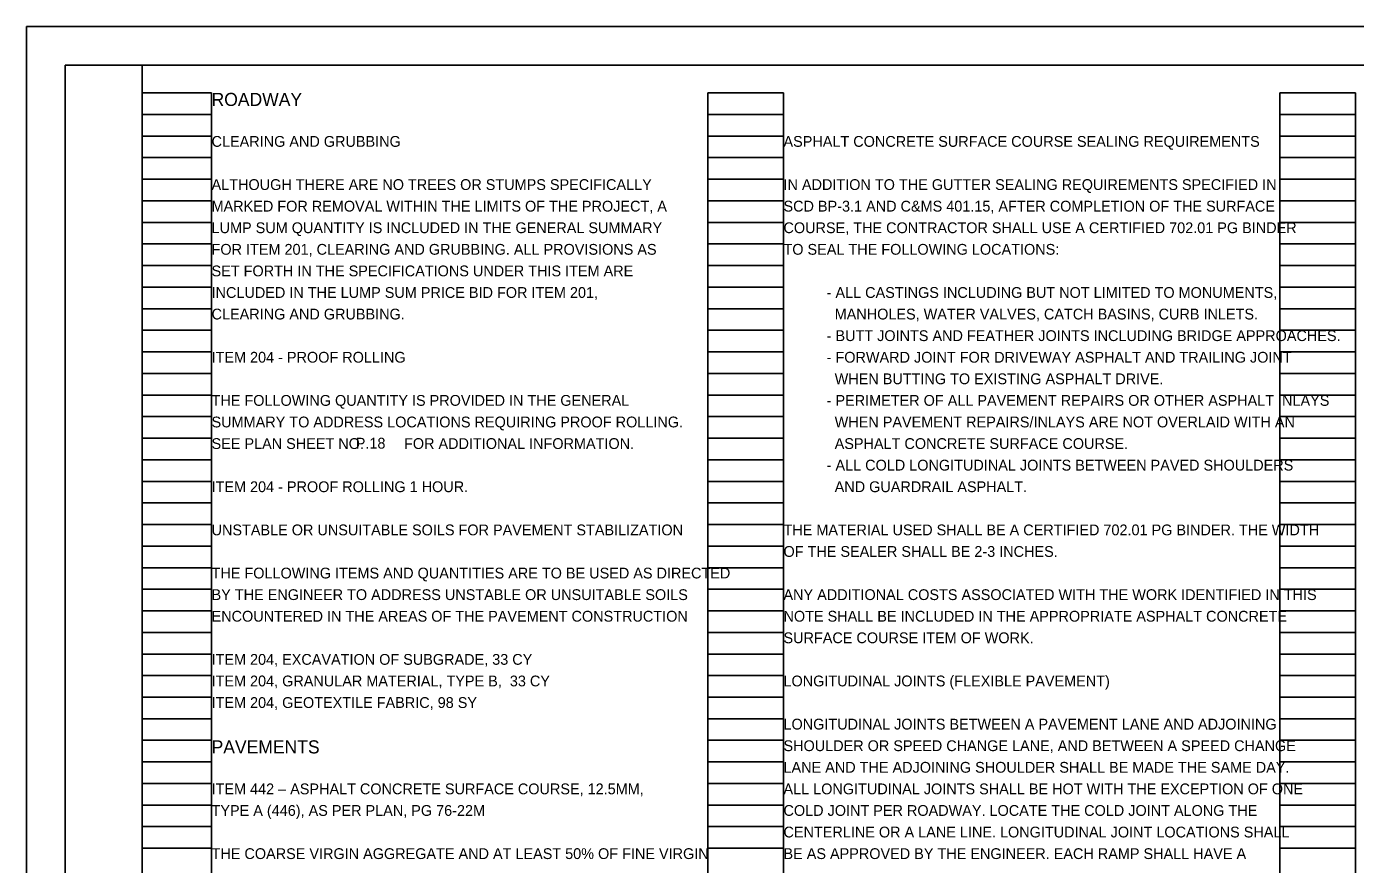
# Model space of a CAD drawing. Extents: x 0 to 34, y -49.5 to 22.
# Drawn here: x 0 to 17.24, y 11.13 to 22 of the extents above; entities that cross this region are included whole.
import ezdxf

# ---------------------------------------------------------------- set-up
doc = ezdxf.new("R2010")
doc.units = 0
for name, color, linetype in [('SH_Border', 7, 'Continuous'), ('SH_Cut_Line', 7, 'Continuous'), ('SH_Data', 7, 'Continuous'), ('SH_Text', 7, 'Continuous')]:
    doc.layers.add(name, color=color, linetype=linetype)

msp = doc.modelspace()

# ---------------------------------------------------------------- linework, layer by layer
at = {"layer": 'SH_Border'}
for points in [[(0.5, 21.5), (1.5, 21.5), (1.5, 0.5), (0.5, 0.5)], [(1.5, 21.5), (33.5, 21.5), (33.5, 0.5), (1.5, 0.5)]]:
    msp.add_lwpolyline(points, close=True, dxfattribs=at)
at = {"layer": 'SH_Cut_Line'}
msp.add_lwpolyline([(0, 0), (34, 0), (34, 22), (0, 22)], close=True, dxfattribs=at)
at = {"layer": 'SH_Data'}
for p, q in [((1.5, 0.98), (1.5, 21.14)), ((1.5, 21.14), (2.4, 21.14)), ((2.4, 0.98), (2.4, 21.14)), ((8.84, 0.98), (8.84, 21.14)), ((8.84, 21.14), (9.82, 21.14)), ((9.82, 0.98), (9.82, 21.14)), ((16.26, 0.98), (16.26, 21.14)), ((16.26, 21.14), (17.24, 21.14)), ((17.24, 0.98), (17.24, 21.14)), ((1.5, 20.86), (2.4, 20.86)), ((8.84, 20.86), (9.82, 20.86)), ((16.26, 20.86), (17.24, 20.86)), ((1.5, 20.58), (2.4, 20.58)), ((8.84, 20.58), (9.82, 20.58)), ((16.26, 20.58), (17.24, 20.58)), ((1.5, 20.3), (2.4, 20.3)), ((8.84, 20.3), (9.82, 20.3)), ((16.26, 20.3), (17.24, 20.3)), ((1.5, 20.02), (2.4, 20.02)), ((8.84, 20.02), (9.82, 20.02)), ((16.26, 20.02), (17.24, 20.02)), ((1.5, 19.74), (2.4, 19.74)), ((8.84, 19.74), (9.82, 19.74)), ((16.26, 19.74), (17.24, 19.74)), ((1.5, 19.46), (2.4, 19.46)), ((8.84, 19.46), (9.82, 19.46)), ((16.26, 19.46), (17.24, 19.46)), ((1.5, 19.18), (2.4, 19.18)), ((8.84, 19.18), (9.82, 19.18)), ((16.26, 19.18), (17.24, 19.18)), ((1.5, 18.9), (2.4, 18.9)), ((8.84, 18.9), (9.82, 18.9)), ((16.26, 18.9), (17.24, 18.9)), ((1.5, 18.62), (2.4, 18.62)), ((8.84, 18.62), (9.82, 18.62)), ((16.26, 18.62), (17.24, 18.62)), ((1.5, 18.34), (2.4, 18.34)), ((8.84, 18.34), (9.82, 18.34)), ((16.26, 18.34), (17.24, 18.34)), ((1.5, 18.06), (2.4, 18.06)), ((8.84, 18.06), (9.82, 18.06)), ((16.26, 18.06), (17.24, 18.06)), ((1.5, 17.78), (2.4, 17.78)), ((8.84, 17.78), (9.82, 17.78)), ((16.26, 17.78), (17.24, 17.78)), ((1.5, 17.5), (2.4, 17.5)), ((8.84, 17.5), (9.82, 17.5)), ((16.26, 17.5), (17.24, 17.5)), ((1.5, 17.22), (2.4, 17.22)), ((8.84, 17.22), (9.82, 17.22)), ((16.26, 17.22), (17.24, 17.22)), ((1.5, 16.94), (2.4, 16.94)), ((8.84, 16.94), (9.82, 16.94)), ((16.26, 16.94), (17.24, 16.94)), ((1.5, 16.66), (2.4, 16.66)), ((8.84, 16.66), (9.82, 16.66)), ((16.26, 16.66), (17.24, 16.66)), ((1.5, 16.38), (2.4, 16.38)), ((8.84, 16.38), (9.82, 16.38)), ((16.26, 16.38), (17.24, 16.38)), ((1.5, 16.1), (2.4, 16.1)), ((8.84, 16.1), (9.82, 16.1)), ((16.26, 16.1), (17.24, 16.1)), ((1.5, 15.82), (2.4, 15.82)), ((8.84, 15.82), (9.82, 15.82)), ((16.26, 15.82), (17.24, 15.82)), ((1.5, 15.54), (2.4, 15.54)), ((8.84, 15.54), (9.82, 15.54)), ((16.26, 15.54), (17.24, 15.54)), ((1.5, 15.26), (2.4, 15.26)), ((8.84, 15.26), (9.82, 15.26)), ((16.26, 15.26), (17.24, 15.26)), ((1.5, 14.98), (2.4, 14.98)), ((8.84, 14.98), (9.82, 14.98)), ((16.26, 14.98), (17.24, 14.98)), ((1.5, 14.7), (2.4, 14.7)), ((8.84, 14.7), (9.82, 14.7)), ((16.26, 14.7), (17.24, 14.7)), ((1.5, 14.42), (2.4, 14.42)), ((8.84, 14.42), (9.82, 14.42)), ((16.26, 14.42), (17.24, 14.42)), ((1.5, 14.14), (2.4, 14.14)), ((8.84, 14.14), (9.82, 14.14)), ((16.26, 14.14), (17.24, 14.14)), ((1.5, 13.86), (2.4, 13.86)), ((8.84, 13.86), (9.82, 13.86)), ((16.26, 13.86), (17.24, 13.86)), ((1.5, 13.58), (2.4, 13.58)), ((8.84, 13.58), (9.82, 13.58)), ((16.26, 13.58), (17.24, 13.58)), ((1.5, 13.3), (2.4, 13.3)), ((8.84, 13.3), (9.82, 13.3)), ((16.26, 13.3), (17.24, 13.3)), ((1.5, 13.02), (2.4, 13.02)), ((8.84, 13.02), (9.82, 13.02)), ((16.26, 13.02), (17.24, 13.02)), ((1.5, 12.74), (2.4, 12.74)), ((8.84, 12.74), (9.82, 12.74)), ((16.26, 12.74), (17.24, 12.74)), ((1.5, 12.46), (2.4, 12.46)), ((8.84, 12.46), (9.82, 12.46)), ((16.26, 12.46), (17.24, 12.46)), ((1.5, 12.18), (2.4, 12.18)), ((8.84, 12.18), (9.82, 12.18)), ((16.26, 12.18), (17.24, 12.18)), ((1.5, 11.9), (2.4, 11.9)), ((8.84, 11.9), (9.82, 11.9)), ((16.26, 11.9), (17.24, 11.9)), ((1.5, 11.62), (2.4, 11.62)), ((8.84, 11.62), (9.82, 11.62)), ((16.26, 11.62), (17.24, 11.62)), ((1.5, 11.34), (2.4, 11.34)), ((8.84, 11.34), (9.82, 11.34)), ((16.26, 11.34), (17.24, 11.34))]:
    msp.add_line(p, q, dxfattribs=at)

# ---------------------------------------------------------------- texts
at = {"layer": 'SH_Text'}
for s, height, p in [('ROADWAY', 0.17, (2.4, 20.97)), ('CLEARING AND GRUBBING', 0.14, (2.4, 20.44)), ('ASPHALT CONCRETE SURFACE COURSE SEALING REQUIREMENTS', 0.14, (9.82, 20.44)), ('ALTHOUGH THERE ARE NO TREES OR STUMPS SPECIFICALLY', 0.14, (2.4, 19.88)), ('IN ADDITION TO THE GUTTER SEALING REQUIREMENTS SPECIFIED IN', 0.14, (9.82, 19.88)), ('MARKED FOR REMOVAL WITHIN THE LIMITS OF THE PROJECT, A', 0.14, (2.4, 19.6)), ('SCD BP-3.1 AND C&MS 401.15, AFTER COMPLETION OF THE SURFACE', 0.14, (9.82, 19.6)), ('LUMP SUM QUANTITY IS INCLUDED IN THE GENERAL SUMMARY', 0.14, (2.4, 19.32)), ('COURSE, THE CONTRACTOR SHALL USE A CERTIFIED 702.01 PG BINDER', 0.14, (9.82, 19.32)), ('FOR ITEM 201, CLEARING AND GRUBBING. ALL PROVISIONS AS', 0.14, (2.4, 19.04)), ('TO SEAL THE FOLLOWING LOCATIONS:', 0.14, (9.82, 19.04)), ('SET FORTH IN THE SPECIFICATIONS UNDER THIS ITEM ARE', 0.14, (2.4, 18.76)), ('INCLUDED IN THE LUMP SUM PRICE BID FOR ITEM 201,', 0.14, (2.4, 18.48)), ('- ALL CASTINGS INCLUDING BUT NOT LIMITED TO MONUMENTS,', 0.14, (10.38, 18.48)), ('CLEARING AND GRUBBING.', 0.14, (2.4, 18.2)), ('  MANHOLES, WATER VALVES, CATCH BASINS, CURB INLETS.', 0.14, (10.38, 18.2)), ('- BUTT JOINTS AND FEATHER JOINTS INCLUDING BRIDGE APPROACHES.', 0.14, (10.38, 17.92)), ('ITEM 204 - PROOF ROLLING', 0.14, (2.4, 17.64)), ('- FORWARD JOINT FOR DRIVEWAY ASPHALT AND TRAILING JOINT', 0.14, (10.38, 17.64)), ('  WHEN BUTTING TO EXISTING ASPHALT DRIVE.', 0.14, (10.38, 17.36)), ('THE FOLLOWING QUANTITY IS PROVIDED IN THE GENERAL', 0.14, (2.4, 17.08)), ('- PERIMETER OF ALL PAVEMENT REPAIRS OR OTHER ASPHALT INLAYS', 0.14, (10.38, 17.08)), ('SUMMARY TO ADDRESS LOCATIONS REQUIRING PROOF ROLLING.', 0.14, (2.4, 16.8)), ('  WHEN PAVEMENT REPAIRS/INLAYS ARE NOT OVERLAID WITH AN', 0.14, (10.38, 16.8)), ('SEE PLAN SHEET NO.          FOR ADDITIONAL INFORMATION.', 0.14, (2.4, 16.52)), ('P.18', 0.14, (4.271, 16.525)), ('  ASPHALT CONCRETE SURFACE COURSE.', 0.14, (10.38, 16.52)), ('- ALL COLD LONGITUDINAL JOINTS BETWEEN PAVED SHOULDERS', 0.14, (10.38, 16.24)), ('ITEM 204 - PROOF ROLLING 1 HOUR.', 0.14, (2.4, 15.96)), ('  AND GUARDRAIL ASPHALT.', 0.14, (10.38, 15.96)), ('UNSTABLE OR UNSUITABLE SOILS FOR PAVEMENT STABILIZATION', 0.14, (2.4, 15.4)), ('THE MATERIAL USED SHALL BE A CERTIFIED 702.01 PG BINDER. THE WIDTH', 0.14, (9.82, 15.4)), ('OF THE SEALER SHALL BE 2-3 INCHES.', 0.14, (9.82, 15.12)), ('THE FOLLOWING ITEMS AND QUANTITIES ARE TO BE USED AS DIRECTED', 0.14, (2.4, 14.84)), ('BY THE ENGINEER TO ADDRESS UNSTABLE OR UNSUITABLE SOILS', 0.14, (2.4, 14.56)), ('ANY ADDITIONAL COSTS ASSOCIATED WITH THE WORK IDENTIFIED IN THIS', 0.14, (9.82, 14.56)), ('ENCOUNTERED IN THE AREAS OF THE PAVEMENT CONSTRUCTION', 0.14, (2.4, 14.28)), ('NOTE SHALL BE INCLUDED IN THE APPROPRIATE ASPHALT CONCRETE', 0.14, (9.82, 14.28)), ('SURFACE COURSE ITEM OF WORK.', 0.14, (9.82, 14)), ('ITEM 204, EXCAVATION OF SUBGRADE, 33 CY', 0.14, (2.4, 13.72)), ('ITEM 204, GRANULAR MATERIAL, TYPE B,  33 CY', 0.14, (2.4, 13.44)), ('LONGITUDINAL JOINTS (FLEXIBLE PAVEMENT)', 0.14, (9.82, 13.44)), ('ITEM 204, GEOTEXTILE FABRIC, 98 SY', 0.14, (2.4, 13.16)), ('LONGITUDINAL JOINTS BETWEEN A PAVEMENT LANE AND ADJOINING', 0.14, (9.82, 12.88)), ('PAVEMENTS', 0.17, (2.4, 12.57)), ('SHOULDER OR SPEED CHANGE LANE, AND BETWEEN A SPEED CHANGE', 0.14, (9.82, 12.6)), ('LANE AND THE ADJOINING SHOULDER SHALL BE MADE THE SAME DAY.', 0.14, (9.82, 12.32)), ('ITEM 442 – ASPHALT CONCRETE SURFACE COURSE, 12.5MM, ', 0.14, (2.4, 12.04)), ('ALL LONGITUDINAL JOINTS SHALL BE HOT WITH THE EXCEPTION OF ONE', 0.14, (9.82, 12.04)), ('TYPE A (446), AS PER PLAN, PG 76-22M', 0.14, (2.4, 11.76)), ('COLD JOINT PER ROADWAY. LOCATE THE COLD JOINT ALONG THE', 0.14, (9.82, 11.76)), ('CENTERLINE OR A LANE LINE. LONGITUDINAL JOINT LOCATIONS SHALL', 0.14, (9.82, 11.48)), ('THE COARSE VIRGIN AGGREGATE AND AT LEAST 50% OF FINE VIRGIN ', 0.14, (2.4, 11.2)), ('BE AS APPROVED BY THE ENGINEER. EACH RAMP SHALL HAVE A', 0.14, (9.82, 11.2))]:
    msp.add_text(s, height=height, dxfattribs=at).set_placement(p)

doc.saveas('drawing.dxf')
